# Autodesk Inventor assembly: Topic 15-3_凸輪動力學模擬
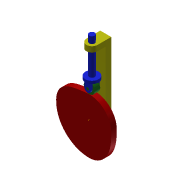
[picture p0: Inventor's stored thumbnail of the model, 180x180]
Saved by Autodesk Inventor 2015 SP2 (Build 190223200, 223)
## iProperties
Created: 2020-03
Part Number: Topic 15-3_凸輪動力學模擬
Document SubType Name: Assembly
Designer: Kuan-Lun Hsu
Author: Kuan-Lun Hsu
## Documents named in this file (5)
- C:\Users\Kuan_Lun Hsu\Desktop\Topic 15-3_凸輪動力學模擬\Topic 15-3_凸輪動力學模擬.iam
- C:\Users\Kuan_Lun Hsu\Desktop\Topic 15-3_凸輪動力學模擬\本體.ipt
- C:\Users\Kuan_Lun Hsu\Desktop\Topic 15-3_凸輪動力學模擬\凸輪.ipt
- C:\Users\Kuan_Lun Hsu\Desktop\Topic 15-3_凸輪動力學模擬\從動桿.ipt
- C:\Users\Kuan_Lun Hsu\Desktop\Topic 15-3_凸輪動力學模擬\滾輪.ipt
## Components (4 placed, 4 different names)
1. 本體:1
2. 圓盤形凸輪:1
3. 從動桿:1
4. 滾輪:1
